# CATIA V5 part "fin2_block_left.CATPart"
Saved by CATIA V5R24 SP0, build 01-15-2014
Part number: Frame Right
Bounding box of the stored display mesh (mm): x -8.75 to 1.25, y -25 to 0, z 0 to 31.822
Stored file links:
  G:\내 드라이브\04_WORK\00_LECTURE\CAD2020\exam\fin2_block_left.CATPart
  G:\내 드라이브\04_WORK\00_LECTURE\CAD2020\exam\fin2_block.CATPart
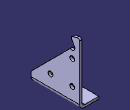
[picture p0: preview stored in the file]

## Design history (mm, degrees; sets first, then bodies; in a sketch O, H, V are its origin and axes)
AxisSystem1: origin (0, 0, 0), X (1, 0, 0), Y (0, 1, 0), Z (0, 0, 1)
Body1 (main body)
  Body2 "Body from original PartBody"
    Solid1: linked copy from another document
  Assemble1: tool Body2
